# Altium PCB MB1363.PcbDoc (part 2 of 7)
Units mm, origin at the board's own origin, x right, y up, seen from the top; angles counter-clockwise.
Board outline 70 x 133.34 mm, 6 copper layers (Top Layer, Signal Layer 1, Signal Layer 2, Signal Layer 3, Signal Layer 4, Bottom Layer), stack 1.57 mm thick; 356 components, 294 nets, 1448 pads, 1107 vias.
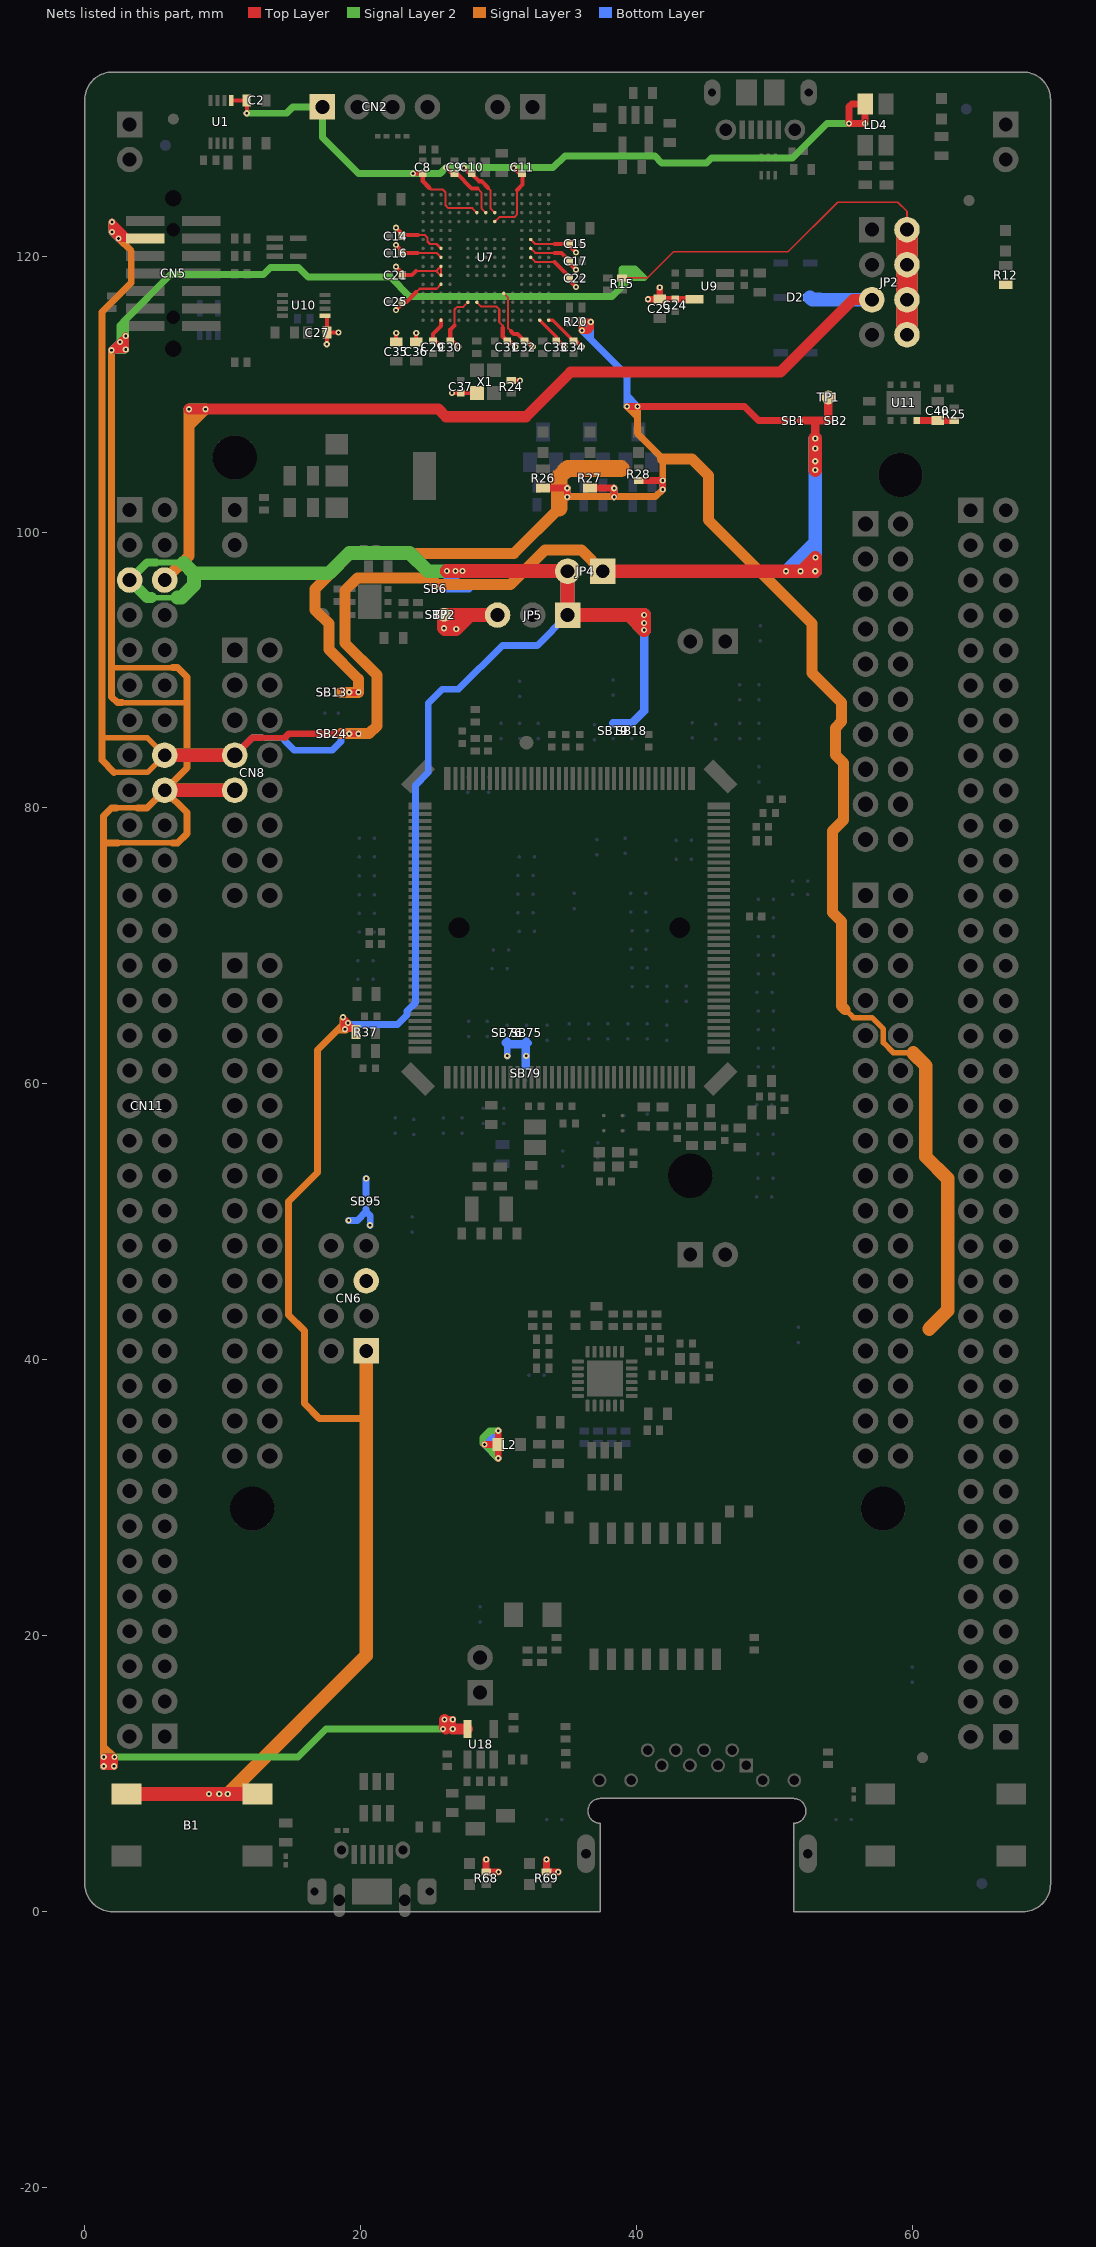
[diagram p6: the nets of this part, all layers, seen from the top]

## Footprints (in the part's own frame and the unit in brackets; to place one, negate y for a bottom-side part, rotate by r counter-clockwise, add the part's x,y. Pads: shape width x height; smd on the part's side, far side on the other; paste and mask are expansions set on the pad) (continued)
ICC_UFBGA201_176+25_10X10_P065 [mm] "IPC"
  round 0.25 smd mask+0.05: A1(-4.55,4.55) A2(-3.9,4.55) A3(-3.25,4.55) A4(-2.6,4.55) A5(-1.95,4.55) A6(-1.3,4.55) A7(-0.65,4.55) A8(0,4.55) A9(0.65,4.55) A10(1.3,4.55) A11(1.95,4.55) A12(2.6,4.55) A13(3.25,4.55) A14(3.9,4.55) A15(4.55,4.55) B1(-4.55,3.9) B2(-3.9,3.9) B3(-3.25,3.9) B4(-2.6,3.9) B5(-1.95,3.9) B6(-1.3,3.9) B7(-0.65,3.9) B8(0,3.9) B9(0.65,3.9) B10(1.3,3.9) B11(1.95,3.9) B12(2.6,3.9) B13(3.25,3.9) B14(3.9,3.9) B15(4.55,3.9) C1(-4.55,3.25) C2(-3.9,3.25) C3(-3.25,3.25) C4(-2.6,3.25) C5(-1.95,3.25) C6(-1.3,3.25) C7(-0.65,3.25) C8(0,3.25) C9(0.65,3.25) C10(1.3,3.25) C11(1.95,3.25) C12(2.6,3.25) C13(3.25,3.25) C14(3.9,3.25) C15(4.55,3.25) D1(-4.55,2.6) D2(-3.9,2.6) D3(-3.25,2.6) D4(-2.6,2.6) D5(-1.95,2.6) D6(-1.3,2.6) D7(-0.65,2.6) D8(0,2.6) D9(0.65,2.6) D10(1.3,2.6) D11(1.95,2.6) D12(2.6,2.6) D13(3.25,2.6) D14(3.9,2.6) D15(4.55,2.6) E1(-4.55,1.95) E2(-3.9,1.95) E3(-3.25,1.95) E4(-2.6,1.95) E12(2.6,1.95) E13(3.25,1.95) E14(3.9,1.95) E15(4.55,1.95) F1(-4.55,1.3) F2(-3.9,1.3) F3(-3.25,1.3) F4(-2.6,1.3) F6(-1.3,1.3) F7(-0.65,1.3) F8(0,1.3) F9(0.65,1.3) F10(1.3,1.3) F12(2.6,1.3) F13(3.25,1.3) F14(3.9,1.3) F15(4.55,1.3) G1(-4.55,0.65) G2(-3.9,0.65) G3(-3.25,0.65) G4(-2.6,0.65) G6(-1.3,0.65) G7(-0.65,0.65) G8(0,0.65) G9(0.65,0.65) G10(1.3,0.65) G12(2.6,0.65) G13(3.25,0.65) G14(3.9,0.65) G15(4.55,0.65) H1(-4.55,0) H2(-3.9,0) H3(-3.25,0) H4(-2.6,0) H6(-1.3,0) H7(-0.65,0) H8(0,0) H9(0.65,0) H10(1.3,0) H12(2.6,0) H13(3.25,0) H14(3.9,0) H15(4.55,0) J1(-4.55,-0.65) J2(-3.9,-0.65) J3(-3.25,-0.65) J4(-2.6,-0.65) J6(-1.3,-0.65) J7(-0.65,-0.65) J8(0,-0.65) J9(0.65,-0.65) J10(1.3,-0.65) J12(2.6,-0.65) J13(3.25,-0.65) J14(3.9,-0.65) J15(4.55,-0.65) K1(-4.55,-1.3) K2(-3.9,-1.3) K3(-3.25,-1.3) K4(-2.6,-1.3) K6(-1.3,-1.3) K7(-0.65,-1.3) K8(0,-1.3) K9(0.65,-1.3) K10(1.3,-1.3) K12(2.6,-1.3) K13(3.25,-1.3) K14(3.9,-1.3) K15(4.55,-1.3) L1(-4.55,-1.95) L2(-3.9,-1.95) L3(-3.25,-1.95) L4(-2.6,-1.95) L12(2.6,-1.95) L13(3.25,-1.95) L14(3.9,-1.95) L15(4.55,-1.95) M1(-4.55,-2.6) M2(-3.9,-2.6) M3(-3.25,-2.6) M4(-2.6,-2.6) M5(-1.95,-2.6) M6(-1.3,-2.6) M7(-0.65,-2.6) M8(0,-2.6) M9(0.65,-2.6) M10(1.3,-2.6) M11(1.95,-2.6) M12(2.6,-2.6) M13(3.25,-2.6) M14(3.9,-2.6) M15(4.55,-2.6) N1(-4.55,-3.25) N2(-3.9,-3.25) N3(-3.25,-3.25) N4(-2.6,-3.25) N5(-1.95,-3.25) N6(-1.3,-3.25) N7(-0.65,-3.25) N8(0,-3.25) N9(0.65,-3.25) N10(1.3,-3.25) N11(1.95,-3.25) N12(2.6,-3.25) N13(3.25,-3.25) N14(3.9,-3.25) N15(4.55,-3.25) P1(-4.55,-3.9) P2(-3.9,-3.9) P3(-3.25,-3.9) P4(-2.6,-3.9) P5(-1.95,-3.9) P6(-1.3,-3.9) P7(-0.65,-3.9) P8(0,-3.9) P9(0.65,-3.9) P10(1.3,-3.9) P11(1.95,-3.9) P12(2.6,-3.9) P13(3.25,-3.9) P14(3.9,-3.9) P15(4.55,-3.9) R1(-4.55,-4.55) R2(-3.9,-4.55) R3(-3.25,-4.55) R4(-2.6,-4.55) R5(-1.95,-4.55) R6(-1.3,-4.55) R7(-0.65,-4.55) R8(0,-4.55) R9(0.65,-4.55) R10(1.3,-4.55) R11(1.95,-4.55) R12(2.6,-4.55) R13(3.25,-4.55) R14(3.9,-4.55) R15(4.55,-4.55)
  silkscreen extent -5.22,-5.07 5.07,5.23, body extent -5.07,-5.07 5.07,5.07, height 0.61
ICC_VQFN24-EPAD_4X4_P050 [mm]
  rrect50% 0.85x0.3 smd mask+0.05: 1(-1.95,1.25) 2(-1.95,0.75) 3(-1.95,0.25) 4(-1.95,-0.25) 5(-1.95,-0.75) 6(-1.95,-1.25) 13(1.95,-1.25) 14(1.95,-0.75) 15(1.95,-0.25) 16(1.95,0.25) 17(1.95,0.75) 18(1.95,1.25)
  rrect50% 0.3x0.85 smd mask+0.05: 7(-1.25,-1.95) 8(-0.75,-1.95) 9(-0.25,-1.95) 10(0.25,-1.95) 11(0.75,-1.95) 12(1.25,-1.95) 19(1.25,1.95) 20(0.75,1.95) 21(0.25,1.95) 22(-0.25,1.95) 23(-0.75,1.95) 24(-1.25,1.95)
  rect 2.6x2.6 smd paste-10 mask+0.05: EP(0,0)
  silkscreen extent -2,-2 2,2, body extent -2.05,-2.05 2.05,2.05, height 1.1
ICC_VSSOP8_DCU_R-PDSO-G8_2X2P30_P050 [mm]
  rect 0.3x0.8 smd mask+0.05: 1(-0.75,-1.55) 2(-0.25,-1.55) 3(0.25,-1.55) 4(0.75,-1.55) 5(0.75,1.55) 6(0.25,1.55) 7(-0.25,1.55) 8(-0.75,1.55)
  silkscreen extent -1.05,-1.2 1.05,1.2, body extent -1.05,-1.62 1.05,1.62, height 0.9
L0603 [mm]
  rect 0.8x0.95 smd mask+0.05: 1(-0.8,0) 2(0.8,0)
  silkscreen extent -1.33,-0.6 1.33,0.6, body extent -0.87,-0.47 0.87,0.47, height 0.95
L0805_H0P9 [mm]
  rect 1.1x1.6 smd mask+0.05: 1(-0.75,0) 2(0.75,0)
  silkscreen extent -0.08,-0.7 0.08,0.7, body extent -1.07,-0.7 1.07,0.7, height 1.2
LED_0603_OSRAM_LG-Q396-PS-35_GREEN_1A2K_H0P4 [mm]
  rect 0.8x0.8 smd mask+0.05: 1(-0.75,0) 2(0.75,0)
  silkscreen extent -0.85,-0.53 1.28,0.53, body extent -0.85,-0.45 0.85,0.45, height 0.6
LED_0603_OSRAM_LS-Q976-NR-1_RED_1A2K_H0P8 [mm]
  rect 0.8x0.8 smd mask+0.05: 1(-0.75,0) 2(0.75,0)
  silkscreen extent -0.85,-0.53 1.28,0.53, body extent -0.85,-0.45 0.85,0.45, height 0.8
LED_0603_OSRAM_LY-Q396-P1Q2-36_YELLOW_1A2K_H0P4 [mm]
  rect 0.8x0.8 smd mask+0.05: 1(-0.75,0) 2(0.75,0)
  silkscreen extent -0.85,-0.53 1.28,0.53, body extent -0.85,-0.45 0.85,0.45, height 0.4
LED_0603_RED [mm]
  rect 0.8x0.8 smd mask+0.05: 1(-0.75,0) 2(0.75,0)
  silkscreen extent -0.25,-0.4 1.25,0.4, body extent -0.8,-0.4 0.8,0.4, height 0.6
LED_0603_VISHAY_VLMS1300-GS08_RED_1A2K_H0P8 [mm]
  rect 0.8x0.8 smd mask+0.05: 1(-0.75,0) 2(0.75,0)
  silkscreen extent -0.85,-0.53 1.28,0.53, body extent -0.85,-0.45 0.85,0.45, height 0.8
LED_BI-GR_HSMF-A201-A00J1 [mm]
  rect 1.1x1.5 smd mask+0.05: 1(-0.75,-1.5) 2(-0.75,1.5) 3(0.75,1.5) 4(0.75,-1.5)
  silkscreen extent -1.65,-1.85 1.65,1.85, body extent -1.5,-1.85 1.5,1.85, height 2.1
MIRE_PLACE_SMD_0P8MM [mm]
  round 0.8 smd paste-10 mask+0.2: 1(0,0)
  Top Layer keep-out circle w0.01: c0,0 r0.804
MOS_SOT23-5L [mm]
  rect 0.6x1.3 smd mask+0.05: 1(-0.95,-1.1) 2(0,-1.1) 3(0.95,-1.1) 4(0.95,1.1) 5(-0.95,1.1)
  silkscreen extent -1.6,-0.95 1.6,0.97, body extent -1.52,-1.25 1.52,1.25, height 1.45
NPN_SOT23 [mm]
  rect 1x1.4 smd mask+0.05: 1(-0.95,-1.1) 2(0.95,-1.1) 3(0,1.1)
  silkscreen extent -1.63,-0.82 1.63,0.82, body extent -1.56,-1.25 1.56,1.25, height 1.1
OSC_NDK_NZ2520SB_4P [mm]
  rect 1x1 smd mask+0.05: 1(-0.825,-0.625) 2(0.825,-0.625) 3(0.825,0.625) 4(-0.825,0.625)
  silkscreen extent -1.43,-1.22 1.2,1.05, body extent -1.3,-1.05 1.3,1.05, height 0.91
R0402 [mm]
  rect 0.51x0.7 smd mask+0.05: 1(-0.45,0) 2(0.45,0)
  silkscreen extent -0.72,-0.43 0.72,0.43, body extent -0.52,-0.3 0.52,0.3, height 0.4
R0603 [mm]
  rect 0.64x1 smd mask+0.05: 1(-0.7,0) 2(0.7,0)
  silkscreen extent -1.05,-0.58 1.05,0.58, body extent -0.9,-0.5 0.9,0.5, height 0.56
REG_SOT23-5L [mm]
  rect 0.6x1.3 smd mask+0.05: 1(-0.95,-1.1) 2(0,-1.1) 3(0.95,-1.1) 4(0.95,1.1) 5(-0.95,1.1)
  silkscreen extent -1.6,-0.95 1.6,0.97, body extent -1.52,-1.25 1.52,1.25, height 1.1
REG_SOT223-TAB [mm]
  rect 1.5x1.65 smd mask+0.05: 1(-2.3,-3.175) 2(0,-3.175) 3(2.3,-3.175)
  rect 3.5x1.65 smd mask+0.05: 4(0,3.175)
  silkscreen extent -3.35,-2.15 3.35,2.12, body extent -3.35,-3.48 3.35,3.48, height 1.8
Sheetbox_6L2S [mil] "Sheetbox 6 layers / 2 silkscreens"
  round 20 on Mech16: 1(813.5,208.05) 1(2736.63,208.05)
SOLDER-BRIDGE_R0402-0R [mil]
  round 10 smd paste-393.7: 1(-17.72,0) 2(20.67,0)
  Top Layer region: 1.48,13.78 8.37,0 1.48,-13.78 30.51,-13.78 30.51,13.78
  Top Layer region: -30.51,-13.78 -30.51,13.78 -8.37,13.78 -1.48,0 -8.37,-13.78
  silkscreen extent -11,-17 11,17, body extent -36,-20 36,20, height 20
SOLDER-BRIDGE_R0603-0R [mil]
  round 10 smd paste-393.7: 1(-19.68,0) 2(23.62,0)
  Top Layer region: -47.24,-19.69 -47.24,19.68 -15.75,19.68 3.94,0 -15.75,-19.69 -47.24,-19.69
  Top Layer region: -5.91,19.68 13.78,0 -5.91,-19.69 47.24,-19.69 47.24,19.68 -5.91,19.68
  silkscreen extent -50,-23 50,23, body extent -36,-20 36,20, height 22
SWI_WEALTHMETAL_TD-0341_4P_BLACK [mm]
  rect 1.52x2.16 smd mask+0.05: 1(-2.25,-4.75) 2(-2.25,4.75) 3(2.25,-4.75) 4(2.25,4.75)
  silkscreen extent -3,-3.5 3,3.5, body extent -3,-5.15 3,5.15, height 7.55
SWI_WEALTHMETAL_TD-0341_4P_BLUE [mm]
  rect 1.52x2.16 smd mask+0.05: 1(-2.25,-4.75) 2(-2.25,4.75) 3(2.25,-4.75) 4(2.25,4.75)
  silkscreen extent -3,-3.5 3,3.5, body extent -3,-5.15 3,5.15, height 7.55
TP_SMD_1MM [mm]
  round 1 smd paste-10 mask+0.05: 1(0,0)
  silkscreen extent -0.7,-0.7 0.7,0.7
TRS_DGKYD_KMS-1102NL [mm]
  rect 0.64x1.55 smd mask+0.05: 1(-4.445,-4.575) 2(-3.175,-4.575) 3(-1.905,-4.575) 4(-0.635,-4.575) 5(0.635,-4.575) 6(1.905,-4.575) 7(3.175,-4.575) 8(4.445,-4.575) 9(4.445,4.575) 10(3.175,4.575) 11(1.905,4.575) 12(0.635,4.575) 13(-0.635,4.575) 14(-1.905,4.575) 15(-3.175,4.575) 16(-4.445,4.575)
  silkscreen extent -6.35,-3.7 6.35,3.7, body extent -6.35,-4.7 6.35,4.7, height 6.3

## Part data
B1: library part MCD-00002, "Non-Open Push-Button 0.1A 24V BLUE", Manufacturer=WEALTHMETAL, Manufacturer_Part_Number=TD0341X-G01-BLU
B2: library part MCD-00001, "Non-Open Push-Button 0.1A 24V BLACK", Manufacturer=WEALTHMETAL, Manufacturer_Part_Number=TD0341X-G01-BLA
C1 C3 C18 C63 C69 C72: library part MCD-00238, "Capacitor, MLCC, 1uF, 6V3, X5R, 10%, 0603, T=0,8mm", Manufacturer=YAGEO, Manufacturer_Part_Number=CC0603KRX5R5BB105, Package=C0603
C2 C4: library part MCD-00211, "Capacitor, MLCC, 100nF, 16V, X7R, 10%, 0603, T=0,8mm", Manufacturer=YAGEO, Manufacturer_Part_Number=CC0603KRX7R7BB104, Package=C0603
C5: library part MCD-00016, "Capacitor, MLCC, 20pF, 50V, NPO, 5%, 0402, T=0,5mm", Manufacturer=YAGEO, Manufacturer_Part_Number=CC0402JRNPO9BN200, Package=C0402
C6: library part MCD-00205, "Capacitor, MLCC, 100pF, 50V, NPO, 5%, 0402, T=0,5mm", Manufacturer=YAGEO, Manufacturer_Part_Number=CC0402JRNPO9BN101, Package=C0402
C7 C12 C13: library part MCD-00012, "Capacitor, MLCC, 2.2uF, 10V, X5R, 10%, 0603, T=0,8mm", Alternate_Manufacturer=KEMET, Alternate_Manufacturer_Part_Number=C0603C225K8PACTU, Manufacturer=YAGEO, Manufacturer_Part_Number=CC0603KRX5R6BB225, Package=C0603
C8 C9 C10 C11 C14 C15 C16 C17 C20 C21 C22 C24 C25 C28 C29 C30 C31 C32 C33 C34 C37: library part MCD-00102, "Capacitor, MLCC, 100nF, 16V, X7R, 10%, 0402, T=0,5mm", Manufacturer=YAGEO, Manufacturer_Part_Number=CC0402KRX7R7BB104, Package=C0402
C19: library part MCD-00011, "Capacitor, MLCC, 10nF, 16V, X7R, 10%, 0402, T=0.5mm", Manufacturer=YAGEO, Manufacturer_Part_Number=CC0402KRX7R7BB103, Package=C0402
C23 C36: library part MCD-00010, "Capacitor, MLCC, 1uF, 16V, X5R, 10%, 0603, T=0,8mm", Manufacturer=YAGEO, Manufacturer_Part_Number=CC0603KRX5R7BB105, Package=C0603
C26 C27 C60 C66 C70 C79 C84 C85 C86 C88 C89: library part MCD-00237, "Capacitor, MLCC, 100nF, 6V3, X5R, 10%, 0603, T=0,8mm", Manufacturer=YAGEO, Manufacturer_Part_Number=CC0603KRX5R5BB104, Package=C0603
C35 C91: library part MCD-00009, "Capacitor, MLCC, 4.7uF, 16V, X5R, 10%, 0603, T=0.8mm", Manufacturer=YAGEO, Manufacturer_Part_Number=CC0603KRX5R7BB475, Package=C0603
C38 C44 C51 C53 C54 C58 C61 C62: library part MCD-00006, "Capacitor, MLCC, 100nF, 16V, X7R, 10%, 0402, T=0.5mm", Manufacturer=YAGEO, Manufacturer_Part_Number=CC0402KRX7R7BB104, Package=C0402
C39 C43 C45 C67: library part MCD-01121, "Capacitor, MLCC, 4.7µF, 10V, X5R, 20%, 0603, T=0,8mm", Manufacturer=MURATA, Manufacturer_Part_Number=GRM188R61A475ME15, Package=C0603
C40: library part MCD-00097, "Capacitor, MLCC, 4.7uF, 16V, X5R, 20%, 0603, T=0,8mm", Alternate_Manufacturer=Murata, Alternate_Manufacturer_Part_Number=GRM188R61C475MAAJ, Manufacturer=MURATA, Manufacturer_Part_Number=GRM188R61C475KE11, Package=C0603
C41 C42: library part MCD-00014, "Capacitor, MLCC, 10uF, 25V, X5R, 10%, 0805, T=0,85mm", Manufacturer=YAGEO, Manufacturer_Part_Number=CC0805KRX5R8BB106, Package=C0805
C46 C47 C48 C49 C50 C52 C55 C56 C57 C59 C71 C73: library part MCD-01123, "Capacitor, MLCC,100nF, 10V, X7R, 10%, 0402, T=0.5mm", Manufacturer=MURATA, Manufacturer_Part_Number=GRM155R71A104KA01, Package=C0402
C64: library part MCD-01225, "Capacitor, MLCC, 220pF, 50V, NPO, 5%, 0402, T=0,5mm", Manufacturer=YAGEO, Manufacturer_Part_Number=CC0402JRNPO9BN221, Package=C0402
C65 C68: library part MCD-01355, "Capacitor, MLCC, 10uF, 4V, X5R, 20%, 0402, T=0,5mm", Manufacturer=MURATA, Manufacturer_Part_Number=GRM155R60G106ME44, Package=C0402
C74 C76 C81 C83: library part MCD-01374, "Capacitor, MLCC, 5.6pF, 50V, NPO, 5%, 0402, T=0,5mm", Manufacturer=YAGEO, Manufacturer_Part_Number=CC0402BRNPO9BN5R6, Package=C0402
C75: library part MCD-01341, "Capacitor, MLCC, 10uF, 6V3, X5R, 20%, 0603, T=0,8mm", Manufacturer=MURATA, Manufacturer_Part_Number=GRM188R60J106ME47D, Package=C0603
C77 C78: library part MCD-01367, "Capacitor,5.1pF,0.25pF,50V,NPO,0603", Manufacturer=YAGEO, Manufacturer_Part_Number=CC0603CRNPO9BN5R1, Package=C0603
C80: library part MCD-00095, "Capacitor, MLCC, 1uF, 6V3, X5R, 10%, 0402, T=0,5mm", Alternate_Manufacturer=MURATA, Alternate_Manufacturer_Part_Number=GRM155R60J105KE19, Manufacturer_Part_Number=GRM155R61E105KA12, Package=C0402
C82: library part MCD-00724, "Capacitor, MLCC, 470pF, 50V, NPO, 5%, 0402, T=0,5mm", Manufacturer=YAGEO, Manufacturer_Part_Number=CC0402JRNPO9BN471, Package=C0402
C87: library part MCD-01124, "Capacitor, MLCC, 10µF, 10V, X5R, 10%, 0603, T=0.8mm", Manufacturer=MURATA, Manufacturer_Part_Number=GRM188R61A106KAAL, Package=C0603
C90: library part MCD-00722, "Capacitor, MLCC, 1nF, 2KV, X7R, 10%, 1206, T=1,25mm", Manufacturer=YAGEO, Manufacturer_Part_Number=CC1206KKX7RDBB102, Package=C1206
CN1: library part MCD-00028, "USB-MICRO-B, 0.65mm, RA, SMT, Bottom Mount,", Manufacturer=MOLEX, Manufacturer_Part_Number=1050170001
CN2: library part MCD-00029, "Header, 4x1, 2,54mm, VR, TH, Height 5.84mm/2.54mm", Manufacturer=SAMTEC, Manufacturer_Part_Number=TSW-104-07-x-S
CN3 CN4 CN15 CN16: library part MCD-00214, "Header, 2x1, 2,54mm, VR, TH, Height 5.84mm/10.16mm", Manufacturer=SAMTEC, Manufacturer_Part_Number=TSW-102-09-x-S
CN5: library part MCD-01226, "Header 5x2, 1.27mm, Dual row, Straight, Surface mount, vertical male connector. 3.05mm lead. Mates with FFSD connector. Footprint compatible with FTSH-107-01-L-DV,-K,-A,-P,-ES (STDC14 MEDIUM)", Manufacturer=SAMTEC, Manufacturer_Part_Number=FTSH-105-01-L-DV-K
CN6: library part MCD-00633, "Header, 4x2, 2,54mm, VR, TH, Height 5.84mm/2.54mm", Manufacturer=SAMTEC, Manufacturer_Part_Number=TSW-104-07-x-D
CN7: library part MCD-01039, "Socket, 10x2, 2.54mm, VR, TH, Height 8.51mm/10mm, Low insertion force.", Manufacturer=SAMTEC, Manufacturer_Part_Number=SSW-110-23-x-D
CN8: library part MCD-01037, "Socket, 8x2, 2.54mm, VR, TH, Height 8.51mm/10mm, Low insertion force.", Manufacturer=SAMTEC, Manufacturer_Part_Number=SSW-108-23-x-D
CN9: library part MCD-01040, "Socket, 15x2, 2.54mm, VR, TH, Height 8.51mm/10mm, Low insertion force.", Manufacturer=SAMTEC, Manufacturer_Part_Number=SSW-115-23-x-D
CN10: library part MCD-01041, "Socket, 17x2, 2.54mm, VR, TH, Height 8.51mm/10mm, Low insertion force", Manufacturer=SAMTEC, Manufacturer_Part_Number=SSW-117-23-x-D
CN11 CN12: library part MCD-01210, "Header, 35x2, 2,54mm, VR, TH, Height 5.84mm/2.54mm", Manufacturer=SAMTEC, Manufacturer_Part_Number=TSW-135-07-x-D
CN13: library part MCD-00661, "USB-MICRO-AB Receptacle, RA, SMT + DIP, Standard, Top Mount, USB certified (symbol & footprint compatible with MCD-00022)", Manufacturer=HIROSE, Manufacturer_Part_Number=ZX62RD-AB-5P8(30)
CN14: library part MCD-00717, "RJ45 jack, single port, with LEDS, Metal shielded dip low profile", Manufacturer="DONGGUAN KEYOUDA ELECTRONIC TECHNOLOGY", Manufacturer_Part_Number=KRJ-CB4.2GYZNL
D1 D2 D3: library part MCD-00034, Manufacturer=STMICROELECTRONICS
JP1: library part MCD-00045, "Header, 2x1, 2,54mm, VR, TH, Height 5.84mm/2.54mm", Manufacturer=SAMTEC, Manufacturer_Part_Number=TSW-102-07-x-S
JP2: library part MCD-00686, "Header, 4x2, 2,54mm, VR, TH, Height 5.84mm/2.54mm - Shunt Fitted 1-2", Manufacturer=SAMTEC, Manufacturer_Part_Number=TSW-104-07-x-D
JP3 JP4 JP6 JP7 JP8: library part MCD-00683, "Header, 2x1, 2,54mm, VR, TH, Height 5.84mm/2.54mm - Shunt Fitted by default", Manufacturer=SAMTEC, Manufacturer_Part_Number=TSW-102-07-x-S
JP5: library part MCD-00684, "Header, 3x1, 2,54mm, VR, TH, Height 5.84mm/2.54mm - Shunt Fitted 1-2 by default", Manufacturer=SAMTEC, Manufacturer_Part_Number=TSW-103-07-F-S
L1: library part MCD-01340, "Inductor, 2.2uH, 20%, Isat 1.2A, DCR 0.228Ohm, 0805", Manufacturer=MURATA, Manufacturer_Part_Number=DFE201210U-2R2M{}P2, Package=L0805
L2: library part MCD-00047, "SMD Chip ferrite bead, 600R@100MHz +/-25%, 350mA, 500mohm DC, 0603, T=0.8mm", Manufacturer=TAI-TECH, Manufacturer_Part_Number=FCM1608KF-601T03
LD1 LD5 LD8: library part MCD-00588, "LED Green, 0603 SMD, Forward Voltage Typ=2V, Max=2.5V", Alternate_Manufacturer="VISHAY SEMICONDUCTOR OPTO DIVISION", Alternate_Manufacturer_Part_Number=VLMTG1300-GS08, Manufacturer="OSRAM OPTO SEMICONDUCTORS", Manufacturer_Part_Number="LG Q396-PS-35", Package="LED 0603"
LD2: library part MCD-01061, "LED Yellow, 0603 SMD, Forward Voltage min=1.7V, Typ=2V, Max=2.3V", Manufacturer="OSRAM OPTO SEMICONDUCTORS", Manufacturer_Part_Number="LY Q396-P1Q2-36"
LD3: library part MCD-00586, "LED Red, 0603 SMD, Forward Voltage Typ=2V, Max=2.5V", Alternate_Manufacturer="VISHAY SEMICONDUCTOR OPTO DIVISION", Alternate_Manufacturer_Part_Number=VLMS1300-GS08, Manufacturer="OSRAM OPTO SEMICONDUCTORS", Manufacturer_Part_Number="LS Q976-NR-1", Package="LED 0603"
LD4: library part MCD-00051, "LED Bicolor", Alternate_Manufacturer=EVERLUCK, Alternate_Manufacturer_Part_Number=LE-RGW35280, Manufacturer="AVAGO TECHNOLOGIES", Manufacturer_Part_Number=HSMF-A201-A00J1
LD6: library part MCD-00049, "LED, Red, 0603", Manufacturer=EVERLIGHT, Manufacturer_Part_Number=19-213-R6C-AP1Q2B/3T, Package="LED 0603"
LD7: library part MCD-00587, "LED Red, 0603 SMD, 2V Forward Voltage", Alternate_Manufacturer="OSRAM OPTO SEMICONDUCTORS", Alternate_Manufacturer_Part_Number="LS Q976-NR-1", Manufacturer=VISHAY, Manufacturer_Part_Number=VLMS1300-GS08, Package="LED 0603"
Q1 Q2 Q3 T1: library part MCD-00073, "NPN Bipolar Transistor", Manufacturer=NXP, Manufacturer_Part_Number=BSR14
R1 R4 R67 R71 R72 R73: library part MCD-00223, "Resistor,100K,0603,1%,1/10W", Manufacturer=YAGEO, Manufacturer_Part_Number=RC0603FR-07100KL, Package=R0603
R2: library part MCD-00070, "Resistor,1K,0603,1%,1/10W", Manufacturer=YAGEO, Manufacturer_Part_Number=RC0603FR-071KL, Package=R0603
R3 R10 R11 R13 R23 R29: library part MCD-00481, "Resistor,47R,0402,1%,1/16W", Manufacturer=YAGEO, Manufacturer_Part_Number=RC0402FR-0747RL, Package=R0402
R5 R17 R21 R70: library part MCD-00119, "Resistor,100R,0402,1%,1/16W", Manufacturer=YAGEO, Manufacturer_Part_Number=RC0402FR-07100RL, Package=R0402
R6: library part MCD-00185, "Resistor,3K,0402,1%,1/16W", Manufacturer=YAGEO, Manufacturer_Part_Number=RC0402FR-073KL, Package=R0402
R7 R36 R37 R38: library part MCD-00220, "Resistor,10K,0603,1%,1/10W", Manufacturer=YAGEO, Manufacturer_Part_Number=RC0603FR-0710KL, Package=R0603
R8 R9 R77: library part MCD-00197, "Resistor,330R,0603,1%,1/10W", Manufacturer=YAGEO, Manufacturer_Part_Number=RC0603FR-07330RL, Package=R0603
R12: library part MCD-00500, "Resistor,620R,0603,1%,1/10W", Manufacturer=YAGEO, Manufacturer_Part_Number=RC0603FR-07620RL, Package=R0603
R14 R18 R20: library part MCD-00065, "Resistor,4K7,0402,1%,1/16W", Alternate_Manufacturer=YAGEO, Alternate_Manufacturer_Part_Number=RT0402FRE074K7L, Manufacturer_Part_Number=RC0402FR-074K7L, Package=R0402
R15: library part MCD-00055, "Resistor,2K7,0402,1%,1/16W", Manufacturer=YAGEO, Manufacturer_Part_Number=RC0402FR-072K7L, Package=R0402
R22 R24 R25 R30 R43 R45 R46 R49 R51 R60 R63 R66: library part MCD-00053, "Resistor,10K,0402,1%,1/16W", Manufacturer=YAGEO, Manufacturer_Part_Number=RC0402FR-0710KL, Package=R0402
R26: library part MCD-00462, "Resistor,360R,0603,1%,1/10W", Manufacturer=YAGEO, Manufacturer_Part_Number=RC0603FR-07360RL, Package=R0603
R27: library part MCD-00354, "Resistor,470R,0603,1%,1/10W", Manufacturer=YAGEO, Manufacturer_Part_Number=RC0603FR-07470RL, Package=R0603
R28 R61 R62 R69: library part MCD-00441, "Resistor,270R,0402,1%,1/16W", Manufacturer=YAGEO, Manufacturer_Part_Number=RC0402FR-07270RL, Package=R0402
R31: library part MCD-00443, "Resistor,27K,0402,1%,1/16W", Manufacturer=YAGEO, Manufacturer_Part_Number=RC0402FR-0727KL, Package=R0402
R32: library part MCD-00493, "Resistor,56K,0402,1%,1/16W", Manufacturer=YAGEO, Manufacturer_Part_Number=RC0402FR-0756KL, Package=R0402
R33 R34 R35 R53: library part MCD-00052, "Resistor,0R,0402,5%,1/16W", Manufacturer=YAGEO, Manufacturer_Part_Number=RC0402JR-070RL, Package=R0402
R39 R40 R41 R42: library part MCD-00056, "Resistor,0R,0603,5%,1/10W", Manufacturer=YAGEO, Manufacturer_Part_Number=RC0603JR-070RL, Package=R0603
R44 R47 R48 R52: library part MCD-00455, "Resistor,33R,0402,1%,1/16W", Manufacturer=YAGEO, Manufacturer_Part_Number=RC0402FR-0733RL, Package=R0402
R50: library part MCD-00068, "Resistor,1K5,0402,1%,1/16W", Manufacturer=YAGEO, Manufacturer_Part_Number=RC0402FR-071K5L, Package=R0402
R54: library part MCD-00723, "Resistor,12K1,0402,1%,1/16W", Manufacturer=YAGEO, Manufacturer_Part_Number=RC0402FR-0712K1L, Package=R0402
R55 R56 R57 R58: library part MCD-00515, "Resistor,75R,0402,1%,1/16W", Manufacturer=YAGEO, Manufacturer_Part_Number=RC0402FR-0775RL, Package=R0402
R59 R64 R65: library part MCD-00063, "Resistor,47K,0402,1%,1/16W", Manufacturer=YAGEO, Manufacturer_Part_Number=RC0402FR-0747KL, Package=R0402
R68: library part MCD-00461, "Resistor,360R,0402,1%,1/16W", Manufacturer=YAGEO, Manufacturer_Part_Number=RC0402FR-07360RL, Package=R0402
R74 R75 R76: library part MCD-00222, "Resistor,47K,0603,1%,1/10W", Manufacturer=YAGEO, Manufacturer_Part_Number=RC0603FR-0747KL, Package=R0603
R78 R79 R80 R81: library part MCD-00565, "Resistor,49R9,0402,1%,1/16W", Manufacturer=YAGEO, Manufacturer_Part_Number=RC0402FR-0749R9L, Package=R0402
SB1 SB2 SB3 SB4 SB5 SB6 SB7 SB8 SB9 SB10 SB11 SB12 SB15 SB16 SB17 SB18 SB19 SB20 SB21 SB22 SB23 SB25 SB26 SB27 SB28 SB29 SB30 SB31 SB32 SB33 SB34 SB35 SB36 SB39 SB40 SB41 SB42 SB43 SB44 SB45 SB46 SB47 SB48 SB49 SB50 SB51 SB52 SB53 SB54 SB55 SB56 SB57 SB58 SB59 SB60 SB61 SB62 SB63 SB64 SB65 SB66 SB67 SB68 SB69 SB70 SB71 SB72 SB73 SB74 SB75 SB76 SB77 SB78 SB79 SB80 SB81 SB82 SB83 SB84 SB85 SB86 SB87 SB88 SB89 SB90 SB91 SB92 SB93 SB94 SB95 SB96 SB97 SB98 SB99 SB100 SB101 SB102 SB103 SB104: library part MCD-00071, "Solder Bridge ON", Manufacturer=YAGEO, Manufacturer_Part_Number=RC0603JR-070RL, Package=SB0603
SB13 SB14 SB24 SB37 SB38: library part MCD-01618, "Solder Bridge 0402 ON", Manufacturer=YAGEO, Manufacturer_Part_Number=RC0402JR-070RL, Package=SB0402
TP1 TP2 TP3 TP4: library part MCD-00074, "Test Point 1mm", Manufacturer=n/a
U1 U10: library part MCD-00264, "Dual bit dual supply bus transceiver", Manufacturer="TEXAS INSTRUMENTS"
U2: library part MCD-00159, "500mA, Enhanced single channel power switches with active high enable pin", Alternate_Manufacturer="TEXAS INSTRUMENTS", Alternate_Manufacturer_Part_Number=TPS2051C, Manufacturer=STMICROELECTRONICS
U3 U4 U20 U22 U23: library part MCD-00170, "ESD protection 6V1", Manufacturer=STMICROELECTRONICS, Manufacturer_Part_Number=ESDALC6V1-1U2
U5: library part MCD-00649, "Common mode filter with ESD protection for USB 2.0 interface", Manufacturer=STMICROELECTRONICS
U6 U21: library part MCD-00251, "High power transient voltage suppressor, 7V breakdown", Manufacturer=STMICROELECTRONICS, Manufacturer_Part_Number=ESDA7P60-1U1M
U7: library part MCD-00596, "STM32F723IEK  (STM32F7) BGA176", Manufacturer=STMICROELECTRONICS, Manufacturer_Part_Number=STM32F723IEK6
U8 U24: library part MCD-00136, "Dual Transil array for ESD protection", Manufacturer=STMICROELECTRONICS
U9: library part MCD-00086, "Ultra low drop-low noise BiCMOS voltage, regulators low ESR capacitors compatible", Manufacturer=STMICROELECTRONICS
U11: library part MCD-01025, "LDO, 3.3V, 1.3A, Very low quiescent current BiCMOS voltage regulator", Manufacturer=STMICROELECTRONICS, Package=DFN6-3x3
U12: library part MCD-00088, "IC REG LDO 5V 0.8A SOT223", Manufacturer=STMICROELECTRONICS, Package=SOT-223
U13: library part MCD-00581, "LDO Linear Voltage Regulator IC Positive Adjustable 1 Output Adjustable 1.3A 6-DFN (3x3)", Manufacturer=STMICROELECTRONICS, Package="DFN6 (3x3)"
U14: library part MCD-01360, "STM32H7A3ZIT6Q, LQFP144 package, 20x20", Manufacturer=STMICROELECTRONICS, Manufacturer_Part_Number=STM32H7A3ZIT6Q, Package="LQFP144 20x20"
U15: library part MCD-00719, "10/100M RMII Ethernet transceiver", Manufacturer=MICROCHIP
U16: library part MCD-00250, "Very low capacitance ESD protection , 4 lines", Manufacturer=STMICROELECTRONICS
U17: library part MCD-00718, "Discrete Magnetic Transformer Module, 16 pins, SMT, 100 Base-TX", Manufacturer="DONGGUAN KEYOUDA ELECTRONIC TECHNOLOGY"
U18: library part MCD-00083, "Enhanced single channel power switches with active low enable pin", Alternate_Manufacturer="TEXAS INSTRUMENTS", Alternate_Manufacturer_Part_Number=TPS2041C, Manufacturer=STMICROELECTRONICS
U19: library part MCD-00163, "Very low capacitance ESD protection", Manufacturer=STMICROELECTRONICS
X1: library part MCD-00597, "Oscillator 25.00Mhz, -+50PPM, 3.3V, Temp -55 to +125°C", Alternate_Manufacturer="AVX CORP/KYOCERA CORP", Alternate_Manufacturer_Part_Number=KC2520B25.0000C10E00, Manufacturer=NDK, Manufacturer_Part_Number="NZ2520SB 25MHz END4869B"
X2 X4: library part MCD-01364, "25MHz Crystal. 2x1.6mm package size. 20ppm. Load capacitance: 6pF. Spec EXS00A-CS11321", Manufacturer=NDK, Manufacturer_Part_Number="NX2016SA 25MHz EXS00A-CS11321", Package=NX2016SA
X3: library part MCD-00091, "Crystal 32.768kHz, 6pF, -+20PPM, R=50K, SMD", Manufacturer=NDK, Manufacturer_Part_Number="NX3215SA 32.768KHz EXS00A-MU00525"

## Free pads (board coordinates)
  round 3.2 hole 3.2 unplated: 0(10.866,105.409) 0(12.136,29.209) 0(43.886,53.339) 0(57.856,29.209) 0(59.126,104.139)

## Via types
v1: diameter 0.45, hole 0.2, Top Layer to Bottom Layer, tented both sides, 1098 vias
v2: diameter 0.6, hole 0.3, Top Layer to Bottom Layer, tented both sides, 9 vias

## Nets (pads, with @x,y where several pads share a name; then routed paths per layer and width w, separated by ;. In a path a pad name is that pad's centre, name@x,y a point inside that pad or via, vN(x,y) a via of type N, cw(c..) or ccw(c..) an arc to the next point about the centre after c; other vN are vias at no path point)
1V2_MCU: SB75.2 SB76.2 SB79.1 SB95.2 | length 6.8
  Bottom Layer w0.4: v1(31.991,62.029) 31.991,62.729 32.215,62.953 SB75.2@32.015,63.153
  Bottom Layer w0.5: SB95.2@20.391,52.034 v1(20.391,53.134) ; v1(30.616,62.029) 30.616,62.879 ; SB76.2@30.616,63.153 30.616,62.879 ; 30.89,62.879 30.616,62.879 ; 31.741,62.879 SB75.2@32.015,63.153
  Bottom Layer w0.6: 30.516,62.979 30.616,62.879 ; 30.89,62.879 31.741,62.879 ; SB79.1@31.966,61.329 31.966,62.953
1V2_VOUTCORE: CN6.5 SB95.1 | length 2.9
  Bottom Layer w0.5: v1(19.121,50.105) 19.762,50.105 20.391,50.734 ; SB95.1@20.391,50.934 20.391,50.734 ; v1(20.666,49.754) 20.691,49.729 20.691,50.434 20.391,50.734
1V8_VDD: JP5.3 SB7.2 TP2.1 | length 15.5
  Top Layer w0.5: TP2.1@26.041,94.004 TP2.1@26.066,93.979
  Top Layer w1: TP2.1@26.041,94.004 v1(26.041,93.029) 26.091,92.979 v1(26.916,92.979) 27.916,93.979 ; TP2.1@26.066,93.979 27.916,93.979 ; JP5.3@29.916,93.979 27.916,93.979
  Signal Layer 2 w0.8: v1(26.041,93.029) 26.091,92.979 v1(26.916,92.979) 27.916,93.979 JP5.3@29.916,93.979
  Signal Layer 3 w0.5: v1(26.041,93.029) 26.866,93.029 v1(26.916,92.979)
  Bottom Layer w0.5: SB7.2@26.041,94.004 26.041,93.854 ; 26.041,93.854 v1@26.891,93.004 ; 26.041,93.854 v1(26.041,93.029) 26.066,93.004 v1@26.891,93.004 ; v1@26.891,93.004 v1(26.916,92.979) 26.916,93.004 v1@26.891,93.004
3V3: CN5.3 CN8.7 CN11.16 JP4.1 SB1.1 SB2.2 SB24.1 TP1.1 | length 182.3
  Top Layer w0.4: 12.845,85.089 14.501,85.089
  Top Layer w0.5: CN5.3@4.389,121.284 CN5.3@3.161,121.284 ; CN8.7@10.866,83.819 12.136,85.089 12.845,85.089 ; 14.501,85.089 14.791,85.379 v1(19.166,85.379) v1(19.841,85.379) ; v1(2.436,121.284) CN5.3@3.161,121.284 ; v1(2.436,121.284) v1(1.966,121.754) v1(1.966,122.479) 2.436,122.009 ; v1(2.436,121.284) 2.436,122.009 ; 2.436,122.009 CN5.3@3.161,121.284
  Top Layer w0.6: SB1.1@51.891,108.079 52.941,108.079 ; v1(52.941,106.779) 52.941,108.079 ; TP1.1@53.891,109.754 SB2.2@53.891,108.079 52.941,108.079
  Top Layer w1: CN11.16@5.786,83.819 CN8.7@10.866,83.819 ; JP4.1@37.536,97.154 v1(50.816,97.154) v1(51.866,97.154) v1@51.966,97.154 ; v1(52.941,104.504) v1(52.941,105.129) v1(52.941,106.054) v1(52.941,106.779) ; v1@51.966,97.154 v1(52.941,97.154) 52.941,98.129 v1@51.966,97.154
  Signal Layer 2 w0.5: v1(1.966,122.479) v1(1.966,121.754) v1(2.436,121.284) ; v1(19.166,85.379) v1(19.841,85.379)
  Signal Layer 2 w0.6: v1(50.816,97.154) v1(51.866,97.154) v1@51.966,97.154 ; v1(52.941,104.504) v1(52.941,105.129) v1(52.941,106.054) v1(52.941,106.779) ; v1@51.966,97.154 v1(52.941,97.154) 52.966,97.179 v1(52.966,98.154) v1@51.966,97.154
  Signal Layer 2 w1: CN11.16@5.786,83.819 CN8.7@10.866,83.819
  Signal Layer 3 w0.4: 1.316,85.079 4.526,85.079 CN11.16@5.786,83.819 4.541,82.574 2.121,82.574
  Signal Layer 3 w0.5: 1.316,85.079 1.236,85.159 ; 2.121,82.574 1.236,83.459 1.236,85.159 ; v1(19.166,85.379) v1(19.841,85.379) ; 1.236,85.159 1.236,115.949 3.366,118.079 3.366,120.354 v1(2.436,121.284) ; v1(2.436,121.284) v1(1.966,121.754) v1(1.966,122.479) 2.436,122.009 v1(2.436,121.284)
  Signal Layer 3 w0.6: v1@50.941,97.154 v1(51.866,97.154) v1@51.966,97.154 ; v1(52.941,104.504) v1(52.941,105.129) v1(52.941,106.054) v1(52.941,106.779) ; v1@51.966,97.154 v1(52.941,97.154) 52.966,97.179 v1(52.966,98.154) v1@51.966,97.154
  Signal Layer 3 w0.8: 18.566,85.379 v1(19.166,85.379) v1(19.841,85.379) 20.591,85.379 21.166,85.954 21.166,89.629 18.841,91.954 18.841,95.757 19.762,96.679 25.041,96.679 25.516,96.204 30.866,96.204 33.366,98.704 35.986,98.704 JP4.1@37.536,97.154
  Bottom Layer w0.4: 12.845,85.089 14.281,85.089 14.466,84.904
  Bottom Layer w0.5: v1(1.966,122.479) v1(1.966,121.754) v1(2.436,121.284) ; CN8.7@10.866,83.819 12.136,85.089 12.845,85.089 ; 14.466,84.904 15.191,84.179 17.929,84.179 18.566,84.816 18.566,85.379 ; SB24.1@18.379,85.379 18.566,85.379 ; v1(19.841,85.379) v1(19.166,85.379) 18.566,85.379
  Bottom Layer w1: v1(50.816,97.154) v1@50.841,97.154 ; v1(52.941,106.779) v1(52.941,106.054) v1(52.941,105.129) v1(52.941,104.504) 52.941,99.254 ; v1@50.841,97.154 v1(51.866,97.154) ; v1@50.841,97.154 52.941,99.254 ; v1(51.866,97.154) v1(52.941,97.154) v1@52.941,98.229 ; v1(51.866,97.154) v1@52.941,98.229 ; v1@52.941,98.229 52.941,99.254
3V3_PER: L2.2 R20.2 R26.2 R27.2 R28.2 R68.2 R69.2 SB1.2 SB13.1 | length 180.7
  Top Layer w0.5: v1(19.166,88.379) v1(19.841,88.379) ; v1(28.966,33.854) L2.2@29.966,33.854 ; v1(29.091,3.779) R68.2@29.091,2.879 v1(29.991,2.879) ; v1(29.966,32.854) L2.2@29.966,33.854 ; v1(29.966,34.854) L2.2@29.966,33.854 ; R26.2@33.216,103.179 v1(34.966,103.179) v1(34.966,102.529) ; v1(33.466,3.779) R69.2@33.466,2.879 v1(34.316,2.879) ; R27.2@36.616,103.179 v1(38.366,103.179) v1(38.366,102.529) ; v1(39.291,109.104) v1(40.066,109.104) 47.816,109.104 48.841,108.079 SB1.2@50.791,108.079 ; R28.2@40.141,103.729 v1(41.891,103.729) v1(41.891,103.079) ; v1(36.041,114.604) 36.491,114.604 36.666,114.779 v1(36.666,115.229) R20.2@36.041,115.229 v1(36.041,114.604)
  Signal Layer 2 w0.5: v1(19.166,88.379) v1(19.841,88.379) ; v1(29.966,32.854) v1(28.966,33.854) 28.84,33.98 28.84,34.336 29.358,34.854 v1(29.966,34.854)
  Signal Layer 3 w0.4: 55.091,65.404 55.701,64.794 57.052,64.794 57.881,63.965 57.881,62.983 58.61,62.254 60.016,62.254 60.041,62.229
  Signal Layer 3 w0.5: v1(34.966,103.179) v1(34.966,102.529) 35.011,102.574 38.321,102.574 v1(38.366,102.529) ; v1(38.366,103.179) v1(38.366,102.529) ; v1(38.366,102.529) 38.399,102.562 41.374,102.562 v1(41.891,103.079) v1(41.891,103.729) 41.891,105.304 40.066,107.129 40.066,108.329 ; 40.066,108.329 v1(40.066,109.104) v1(39.291,109.104) 40.066,108.329
  Signal Layer 3 w0.8: 18.566,88.379 v1(19.166,88.379) v1(19.841,88.379) 19.841,89.329 17.691,91.479 17.691,93.354 16.691,94.354 16.691,95.854 19.266,98.429 31.091,98.429 34.391,101.729 ; 41.891,105.304 44.016,105.304 45.216,104.104 45.216,100.854 52.716,93.354 52.716,89.779 54.841,87.654 54.841,86.254 54.396,85.809 54.396,83.839 54.986,83.249 54.986,79.122 54.196,78.332 54.196,72.42 54.841,71.775 54.841,65.654 55.091,65.404
  Signal Layer 3 w1: 60.041,62.229 60.951,61.319 60.951,54.719 62.541,53.129 62.541,43.566 61.2,42.225
  Signal Layer 3 w1.2: 34.391,101.729 34.391,104.004 34.991,104.604 38.866,104.604 38.891,104.579
  Bottom Layer w0.5: 18.566,88.379 v1(19.166,88.379) v1(19.841,88.379) ; v1(29.966,32.854) v1(28.966,33.854) v1(29.966,34.854) ; v1(34.966,102.529) v1(34.966,103.179) ; v1(38.366,102.529) v1(38.366,103.179) ; v1(41.891,103.079) v1(41.891,103.729) ; v1(36.041,114.604) 36.641,114.604 36.666,114.579 ; v1(36.041,114.604) 36.666,113.979 ; v1(36.041,114.604) v1(36.666,115.229) 36.666,114.579 ; 36.666,113.979 36.666,114.579 ; 36.666,113.979 39.291,111.354 39.291,109.879 ; 39.291,109.879 v1(39.291,109.104) v1(40.066,109.104) 39.291,109.879
3V3_STLK: C2.2 C8.2 C9.2 C10.2 C11.2 C14.2 C15.2 C16.2 C17.2 C21.2 C22.2 C23.2 C24.2 C25.2 C27.2 C29.2 C30.2 C31.2 C32.2 C33.2 C34.2 C35.2 C36.2 C37.2 CN2.1 LD4.4 R24.1 U1.1 U7.C1 U7.C5 U7.C6 U7.C7 U7.C8 U7.C9 U7.F3 U7.G3 U7.G13 U7.H13 U7.J12 U7.J13 U7.K4 U7.N8 U7.N9 U7.N10 U7.P1 U7.R1 U9.5 U10.1 X1.4 | length 142.1
  Top Layer w0.15: 23.996,118.924 25.486,118.924 U7.C7@25.816,119.254 25.816,118.634 U7.C6@25.825,118.625 ; 24.016,117.379 24.271,117.634 25.496,117.634 U7.C5@25.816,117.954 ; 24.116,120.229 25.491,120.229 U7.C8@25.816,119.904 ; 24.141,121.529 24.644,121.529 24.836,121.336 24.836,121.059 25.016,120.879 25.491,120.879 U7.C9@25.816,120.554 ; 24.966,124.954 25.091,124.829 25.941,124.829 26.146,124.624 26.146,123.671 26.339,123.479 28.091,123.479 U7.G13@28.416,123.154 ; 25.471,118.916 U7.C6@25.801,118.586 ; 26.791,114.979 26.791,116.131 26.984,116.324 27.436,116.324 U7.F3@27.766,116.654 ; U7.G3@28.416,116.654 28.736,116.334 29.839,116.334 30.036,116.136 30.036,115.209 30.291,114.954 30.291,114.779 ; 28.466,124.904 28.746,124.624 28.746,123.474 U7.H13@29.066,123.154 ; 29.216,124.954 29.396,124.774 29.396,123.474 U7.J13@29.716,123.154 ; U7.J12@29.716,122.504 30.041,122.829 31.144,122.829 31.336,123.021 31.336,124.799 31.341,124.804 ; U7.K4@30.366,117.304 30.686,116.984 30.686,114.759 30.891,114.554 ; U7.N8@32.316,119.904 32.641,119.579 34.041,119.579 ; U7.N9@32.316,120.554 32.641,120.229 34.041,120.229 ; U7.N10@32.316,121.204 32.641,120.879 34.041,120.879
  Top Layer w0.25: U7.P1@32.966,115.354 34.166,114.154 C33.2@34.166,113.854 ; U7.R1@33.616,115.354 33.916,115.354 C34.2@35.416,113.854
  Top Layer w0.3: U1.1@10.616,131.279 C2.2@11.741,131.279 v1(11.741,130.354) ; U10.1@17.416,115.679 17.541,115.554 C27.2@17.541,114.454 ; v1(17.541,113.604) C27.2@17.541,114.454 ; v1(18.391,114.454) C27.2@17.541,114.454 ; v1(22.562,116.083) 22.991,116.512 C25.2@22.991,116.679 23.316,116.679 24.016,117.379 ; v1(22.562,119.225) 22.991,118.796 C21.2@22.991,118.629 23.701,118.629 23.996,118.924 ; v1(22.562,120.8) 22.991,120.371 C16.2@22.991,120.204 23.016,120.229 24.116,120.229 ; v1(22.562,122.05) 22.991,121.621 C14.2@22.991,121.454 23.066,121.529 24.141,121.529 ; C35.2@22.566,113.779 v1(22.566,114.429) ; v1(23.791,125.979) C8.2@24.491,125.979 24.491,125.429 24.966,124.954 ; C36.2@24.016,113.779 v1(24.016,114.429) ; U7.C1@25.816,115.354 25.816,114.929 25.241,114.354 C29.2@25.241,113.854 25.408,113.854 v1(25.837,113.425) ; v1(26.195,126.408) 26.624,125.979 C9.2@26.791,125.979 26.966,125.979 28.041,124.904 28.466,124.904 ; v1(26.616,110.079) C37.2@27.241,110.079 X1.4@28.416,110.079 ; 26.791,114.979 26.491,114.679 C30.2@26.491,113.854 26.658,113.854 v1(27.087,113.425) ; v1(27.47,126.408) 27.899,125.979 C10.2@28.041,125.979 ; C10.2@28.066,125.979 C10.2@28.041,125.979 ; 29.216,124.954 28.741,125.429 28.579,125.429 28.041,125.967 C10.2@28.041,125.979 ; 30.291,114.779 30.291,114.179 C31.2@30.616,113.854 30.783,113.854 v1(31.212,113.425) ; 30.891,114.554 31.086,114.359 31.361,114.359 C32.2@31.866,113.854 32.033,113.854 v1(32.462,113.425) ; R24.1@30.916,110.979 v1(31.541,110.979) ; v1(31.095,126.408) 31.524,125.979 C11.2@31.691,125.979 31.716,125.954 31.716,125.179 31.341,124.804 ; 34.041,119.579 35.141,118.479 C22.2@35.141,118.379 C22.2@35.166,118.354 ; 34.041,120.229 34.541,120.229 C17.2@35.141,119.629 C17.2@35.166,119.604 ; 34.041,120.879 C15.2@35.141,120.879 C15.2@35.166,120.854 ; C33.2@34.166,113.854 34.333,113.854 v1(34.762,113.425) ; C22.2@35.141,118.354 C22.2@35.166,118.354 ; C17.2@35.141,119.604 C17.2@35.166,119.604 ; C15.2@35.141,120.854 C15.2@35.166,120.854 ; C34.2@35.416,113.854 35.583,113.854 v1(36.012,113.425) ; v1(35.595,117.758) 35.166,118.187 C22.2@35.166,118.354 ; v1(35.595,119.008) 35.166,119.437 C17.2@35.166,119.604 ; v1(35.595,120.258) 35.166,120.687 C15.2@35.166,120.854
  Top Layer w0.45: v1(40.816,116.879) C23.2@41.666,116.879 ; v1(41.666,117.729) C23.2@41.666,116.879 ; U9.5@44.191,116.879 C24.2@42.791,116.879 C23.2@41.666,116.879
  Top Layer w0.5: v1(55.391,129.604) 55.391,130.829 55.591,131.029 LD4.4@56.566,131.029 56.541,131.004 v1(56.541,129.604) v1(55.391,129.604)
  Signal Layer 2 w0.5: v1(11.741,130.354) 14.616,130.354 15.071,130.809 CN2.1@17.216,130.809 17.216,128.604 19.846,125.974 25.761,125.974 v1(26.195,126.408) v1(27.47,126.408) v1(31.095,126.408) 33.945,126.408 34.791,127.254 41.316,127.254 41.816,126.754 45.066,126.754 45.411,127.099 51.286,127.099 53.791,129.604 v1(55.391,129.604) v1(56.541,129.604)
3V3_VDD: B1.1 B1.2 CN6.1 CN11.5 JP4.2 JP5.1 R37.2 SB6.1 SB18.2 SB19.2 | length 226.1
  Top Layer w0.4: v1@19.016,63.954 19.066,64.004 v1(19.066,64.404) ; v1@19.016,63.954 v1(18.866,63.954) 18.816,63.954 18.716,64.054 v1(18.716,64.829) 19.066,64.479 v1(19.066,64.404) ; v1@19.016,63.954 19.465,63.954 R37.2@19.666,63.753 19.666,63.804 v1(19.066,64.404)
  Top Layer w1: B1.1@3.017,8.523 v1(8.991,8.523) v1(9.741,8.523) v1(10.366,8.523) B1.2@12.517,8.523 ; v1(26.241,97.179) v1(26.866,97.179) v1(27.366,97.179) 34.971,97.179 JP4.2@34.996,97.154 JP5.1@34.996,93.979 39.466,93.979 ; 39.466,93.979 40.016,93.979 ; 39.466,93.979 v1(40.541,92.904) v1(40.541,93.404) v1@40.541,93.454 ; 40.016,93.979 v1@40.541,93.454 ; 40.016,93.979 v1(40.541,93.979) v1@40.541,93.454
  Signal Layer 2 w0.4: 4.846,95.249 6.701,95.249 ; v1(18.716,64.829) 18.716,64.754 v1(19.066,64.404) 18.866,64.204 v1(18.866,63.954)
  Signal Layer 2 w0.45: 5.154,97.789 7.126,97.789
  Signal Layer 2 w0.5: v1(8.991,8.523) v1(9.741,8.523) v1(10.366,8.523)
  Signal Layer 2 w0.6: CN11.5@3.246,96.519 4.516,97.789 5.154,97.789 ; 7.126,97.789 7.136,97.779
  Signal Layer 2 w0.8: CN11.5@3.246,96.519 4.516,95.249 4.846,95.249
  Signal Layer 2 w1: 6.701,95.249 7.011,95.249 7.911,96.149 7.911,97.004 ; 7.136,97.779 7.911,97.004 ; 7.911,97.004 17.691,97.004 19.166,98.479 23.541,98.479 24.866,97.154 JP4.2@34.996,97.154 JP5.1@34.996,93.979 39.466,93.979 ; 39.466,93.979 v1(40.541,92.904) v1(40.541,93.404) v1(40.541,93.979) 39.466,93.979
  Signal Layer 3 w0.3: v1@18.716,64.754 v1(18.716,64.829)
  Signal Layer 3 w0.5: v1@18.916,63.899 18.311,63.899 ; v1@19.066,64.004 v1(19.066,64.404) 18.716,64.754 18.716,64.304 18.311,63.899 ; 20.391,35.754 16.991,35.754 15.916,36.829 15.916,42.104 14.766,43.254 14.766,51.479 16.866,53.579 16.866,62.454 18.311,63.899 ; v1(26.241,97.179) v1(26.866,97.179) v1(27.366,97.179)
  Signal Layer 3 w0.6: v1(40.541,92.904) v1(40.541,93.404) v1(40.541,93.979)
  Signal Layer 3 w1: v1(8.991,8.523) v1(9.741,8.523) v1(10.366,8.523) 20.391,18.548 20.391,35.754 CN6.1@20.391,40.639
  Bottom Layer w0.3: v1(18.716,64.829) 18.716,64.754 v1(19.066,64.404) 19.066,64.004 19.016,63.954 v1(18.866,63.954)
  Bottom Layer w0.5: v1(19.066,64.404) 19.161,64.309 22.671,64.309 23.366,65.004 23.366,65.279 23.966,65.879 23.966,81.629 24.891,82.554 24.891,87.579 25.916,88.604 27.091,88.604 30.266,91.779 32.796,91.779 JP5.1@34.996,93.979 ; 27.866,95.879 SB6.1@25.941,95.879 25.941,95.929 26.241,96.229 26.241,96.754 ; 26.241,96.754 26.341,96.854 27.041,96.854 v1(27.366,97.179) v1(26.866,97.179) v1(26.241,97.179) 26.241,96.754
  Bottom Layer w0.6: SB19.2@38.291,86.129 SB18.2@39.641,86.129 40.541,87.029 v1(40.541,92.904) v1(40.541,93.404) v1(40.541,93.979)
  Bottom Layer w1: v1(8.991,8.523) v1(9.741,8.523) v1(10.366,8.523) ; JP5.1@34.996,93.979 JP4.2@34.996,97.154
5V: C40.2 CN8.9 CN11.18 JP2.2 JP2.4 JP2.6 JP2.8 R12.2 R15.1 R25.2 U11.6 U18.5 | length 319.9
  Top Layer w0.12: R15.1@38.941,118.429 40.791,118.429 42.666,120.304 50.966,120.304 54.566,123.904 58.93,123.904 59.59,123.244 JP2.2@59.59,121.919
  Top Layer w0.45: v1(2.541,113.779) 2.956,114.194 v1(2.966,114.204)
  Top Layer w0.5: v1(1.941,113.179) v1(2.541,113.779) ; v1(2.141,11.204) 2.141,10.554 v1(2.116,10.529) v1(1.366,10.529) ; v1@2.956,114.194 2.966,114.194 2.966,113.804 ; U18.5@27.736,13.229 U18.5@27.741,13.224 ; U11.6@60.298,108.076 61.813,108.076 C40.2@61.816,108.079 R25.2@63.016,108.079 ; v1(1.366,10.529) 2.041,11.204 v1(1.366,11.204) v1(1.366,10.529) ; 2.391,113.229 2.341,113.179 1.954,113.179 2.004,113.229 2.391,113.229 ; 2.391,113.229 v1(2.966,113.229) 2.966,113.804 ; 2.391,113.229 2.966,113.804 ; v1(25.966,13.229) 26.066,13.329 v1(26.666,13.929) ; v1(25.966,13.229) 26.166,13.229 v1(26.666,13.229) v1(26.666,13.929) ; v1(25.966,13.229) 25.966,13.829 v1(26.066,13.929) v1(26.666,13.929)
  Top Layer w0.8: v1(26.066,13.929) 26.066,13.329 v1@26.166,13.229 ; v1(26.666,13.229) U18.5@27.736,13.229
  Top Layer w1: CN11.18@5.786,81.279 CN8.9@10.866,81.279
  Top Layer w1.5: JP2.8@59.59,114.299 JP2.6@59.59,116.839 JP2.4@59.59,119.379 JP2.2@59.59,121.919
  Signal Layer 2 w0.5: v1(1.941,113.179) v1@1.966,113.179 ; v1(26.666,13.229) v1(25.966,13.229) ; 40.541,118.429 40.516,118.429 ; v1@1.466,10.529 v1(2.116,10.529) 2.116,11.179 v1@1.466,10.529 ; v1@1.466,10.529 v1(1.366,10.529) v1(1.366,11.204) v1(2.141,11.204) 15.441,11.204 17.466,13.229 v1(25.966,13.229) ; v1@1.966,113.179 2.916,113.179 v1(2.966,113.229) v1@2.966,113.354 ; v1@1.966,113.179 1.966,113.204 v1(2.541,113.779) ; v1(2.541,113.779) v1@2.966,113.354 ; v1(2.541,113.779) v1(2.966,114.204) ; v1(2.541,113.779) 2.541,114.979 2.966,115.404 ; v1@2.966,113.354 v1(2.966,114.204) ; v1(2.966,114.204) 2.966,115.404 ; 2.966,115.404 6.216,118.654 12.941,118.654 13.466,119.179 15.491,119.179 16.191,118.479 22.141,118.479 23.541,117.079 38.216,117.079 38.941,117.804 ; v1(25.966,13.229) 25.966,13.829 v1(26.066,13.929) ; v1(26.066,13.929) v1(26.666,13.929) 26.666,13.329 v1(26.066,13.929) ; 38.941,117.804 38.941,118.429 ; 38.941,117.804 39.566,118.429 ; 38.941,118.429 38.941,119.054 ; 38.941,118.429 39.566,118.429 ; 38.941,119.054 39.466,119.054 ; 38.941,119.054 39.566,118.429 ; 39.466,119.054 40.091,118.429 ; 39.466,119.054 39.891,119.054 40.516,118.429 ; 39.566,118.429 40.091,118.429 ; 40.091,118.429 40.516,118.429
  Signal Layer 2 w1: CN11.18@5.786,81.279 CN8.9@10.866,81.279
  Signal Layer 2 w1.5: JP2.8@59.59,114.299 JP2.6@59.59,116.839 JP2.4@59.59,119.379 JP2.2@59.59,121.919
  Signal Layer 3 w0.4: 1.941,90.179 1.951,90.169 6.347,90.169 ; 2.286,80.009 3.807,80.009 ; 2.401,77.469 6.347,77.469 ; 2.685,87.629 7.416,87.629 7.441,87.654
  Signal Layer 3 w0.5: 2.286,80.009 1.946,80.009 1.366,79.429 1.366,77.454 ; 2.401,77.469 1.381,77.469 1.366,77.454 ; 2.685,87.629 2.366,87.629 1.941,88.054 1.941,90.179 v1(1.941,113.179) v1@1.991,113.229 ; v1@2.941,113.254 2.541,113.654 v1(2.541,113.779) ; 3.807,80.009 4.516,80.009 CN11.18@5.786,81.279 ; 6.347,77.469 6.731,77.469 7.391,78.129 7.391,79.674 CN11.18@5.786,81.279 ; 6.347,90.169 6.726,90.169 7.416,89.479 7.416,87.629 7.416,82.909 CN11.18@5.786,81.279 ; v1(1.366,11.204) v1(1.366,10.529) v1@1.466,10.529 ; v1(1.366,11.204) v1(2.141,11.204) 1.366,11.979 ; v1(1.366,11.204) 1.366,11.979 ; 1.366,11.979 1.366,77.454 ; v1@1.466,10.529 v1(2.116,10.529) 2.116,11.179 v1@1.466,10.529 ; v1@1.991,113.229 v1(2.541,113.779) ; v1@1.991,113.229 v1(2.966,113.229) v1(2.966,114.204) v1(2.541,113.779) ; v1(26.066,13.929) v1(26.666,13.929) v1@26.666,13.329 ; v1(26.066,13.929) 25.966,13.829 v1(25.966,13.229) v1(26.666,13.229) v1@26.666,13.329 ; v1(26.066,13.929) v1@26.666,13.329
  Signal Layer 3 w1.5: JP2.8@59.59,114.299 JP2.6@59.59,116.839 JP2.4@59.59,119.379 JP2.2@59.59,121.919
  Bottom Layer w0.5: v1(2.141,11.204) v1(1.366,11.204) v1(1.366,10.529) v1@1.491,10.529 ; v1(26.066,13.929) 25.966,13.829 v1(25.966,13.229) v1(26.666,13.229) v1@26.666,13.354 ; v1@1.491,10.529 v1(2.116,10.529) 2.116,11.154 v1@1.491,10.529 ; v1(2.541,113.779) 2.541,113.654 v1(2.966,113.229) ; v1(2.541,113.779) v1(1.941,113.179) 2.916,113.179 v1(2.966,113.229) ; v1(2.541,113.779) v1(2.966,114.204) v1(2.966,113.229) ; v1@26.666,13.354 v1(26.666,13.929) 26.091,13.929 v1@26.666,13.354
  Bottom Layer w1.5: JP2.8@59.59,114.299 JP2.6@59.59,116.839 JP2.4@59.59,119.379 JP2.2@59.59,121.919
5V_EXT: CN11.6 D2.1 JP2.5 | length 73.8
  Top Layer w0.8: v1(7.541,108.904) v1(8.741,108.904) 25.641,108.904 26.191,108.354 31.991,108.354 35.221,111.584 50.421,111.584 55.676,116.839 JP2.5@57.05,116.839
  Signal Layer 3 w0.8: CN11.6@5.786,96.519 7.541,98.274 7.541,107.704 ; 7.541,107.704 v1(7.541,108.904) v1(8.741,108.904) 7.541,107.704
  Bottom Layer w1: D2.1@52.57,117 52.72,116.85 53.245,116.85 53.256,116.839 JP2.5@57.05,116.839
